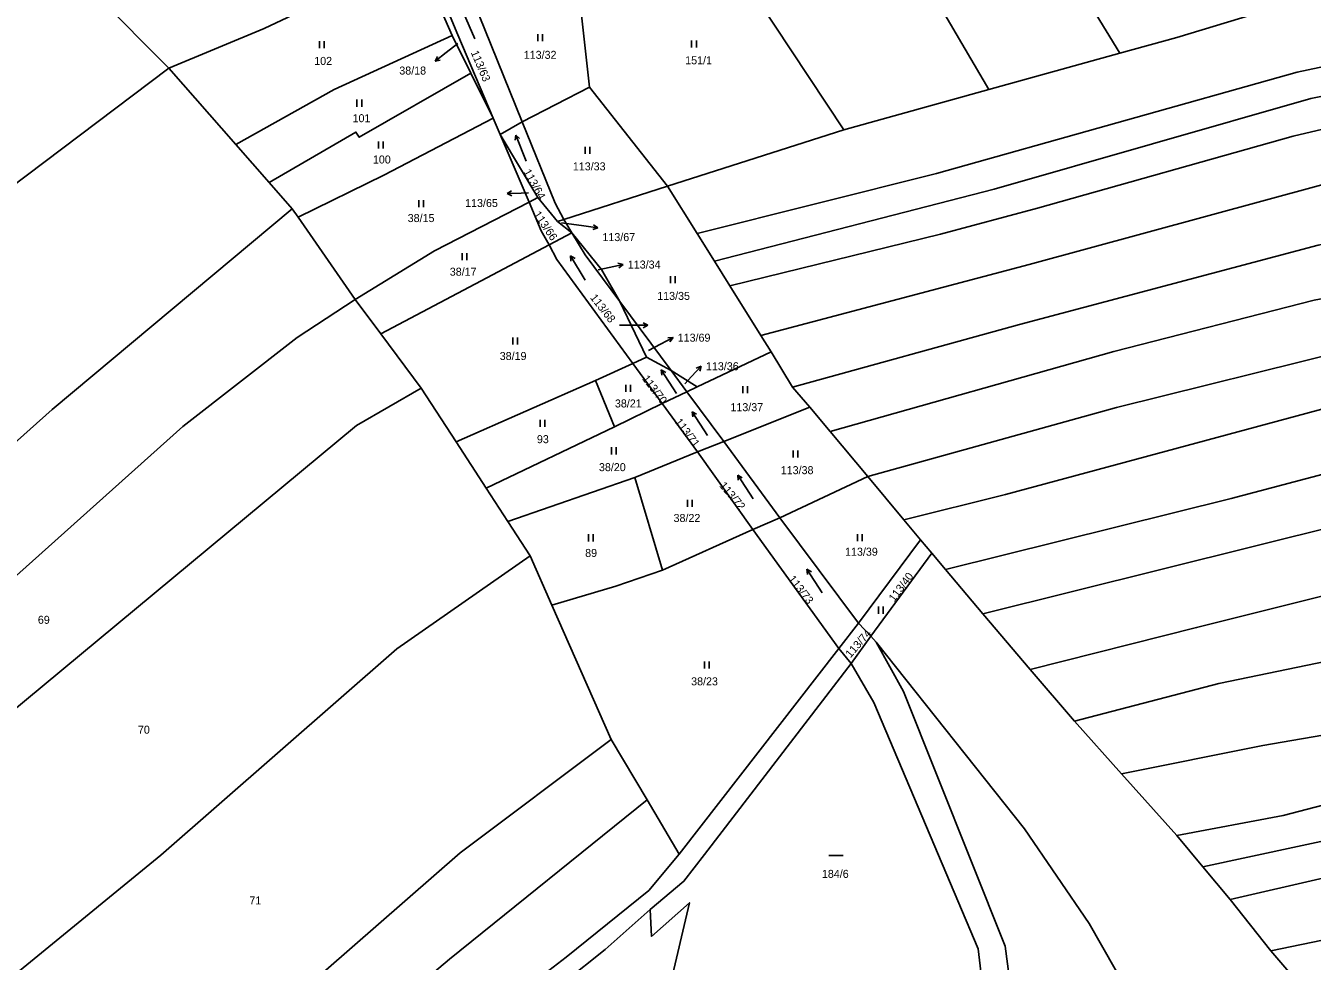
# Model space of a CAD drawing. Extents: x -7483133 to -743907, y -11317770 to -1129777.
# Drawn here: x -747509.1 to -747235.8, y -1131378.7 to -1131180 of the extents above; entities that cross this region are included whole.
import ezdxf

# ---------------------------------------------------------------- set-up
doc = ezdxf.new("R2010")
doc.units = 0
for name, color, linetype in [('Hranice parcel', 7, 'Continuous'), ('Parcelní čísla', 7, 'Continuous'), ('Pop  PČ popisy', 7, 'Continuous'), ('Značky kultur', 7, 'Continuous')]:
    doc.layers.add(name, color=color, linetype=linetype)

msp = doc.modelspace()

# ---------------------------------------------------------------- linework, layer by layer
at = {"layer": 'Hranice parcel'}
for p, q in [((-747414.16, -1131174.44), (-747403.63, -1131200.37)), ((-747389.33, -1131193.02), (-747391.42, -1131174.47)), ((-747420.83, -1131176.75), (-747418.53, -1131182.09)), ((-747418.53, -1131182.09), (-747414.55, -1131190.08)), ((-747304.55, -1131193.5), (-747276.68, -1131185.78)), ((-747464.5, -1131205.17), (-747478.68, -1131189)), ((-747414.55, -1131190.08), (-747409.79, -1131199.63)), ((-747403.63, -1131200.37), (-747389.33, -1131193.02)), ((-747372.79, -1131214.07), (-747389.33, -1131193.02)), ((-747335.3, -1131202.07), (-747304.55, -1131193.5)), ((-747408.32, -1131203.08), (-747409.79, -1131199.63)), ((-747408.32, -1131203.08), (-747403.63, -1131200.37)), ((-747402.18, -1131217.46), (-747408.32, -1131203.08)), ((-747408.32, -1131203.08), (-747400.3, -1131216.43)), ((-747372.79, -1131214.07), (-747335.3, -1131202.07)), ((-747457.41, -1131213.25), (-747464.5, -1131205.17)), ((-747452.5, -1131218.84), (-747457.41, -1131213.25)), ((-747394.81, -1131221.1), (-747372.79, -1131214.07)), ((-747366.49, -1131224.14), (-747372.79, -1131214.07)), ((-747402.18, -1131217.46), (-747400.3, -1131216.43)), ((-747400.3, -1131216.43), (-747396.13, -1131221.54)), ((-747451.24, -1131220.66), (-747452.5, -1131218.84)), ((-747451.24, -1131220.66), (-747439.12, -1131238.12)), ((-747396.13, -1131221.54), (-747394.81, -1131221.1)), ((-747393.08, -1131223.94), (-747396.13, -1131221.54)), ((-747394.81, -1131221.1), (-747393.08, -1131223.94)), ((-747397.95, -1131226.54), (-747393.08, -1131223.94)), ((-747362.83, -1131229.98), (-747366.49, -1131224.14)), ((-747359.55, -1131235.22), (-747362.83, -1131229.98)), ((-747352.93, -1131245.79), (-747359.55, -1131235.22)), ((-747439.12, -1131238.12), (-747433.68, -1131245.43)), ((-747377.23, -1131250.36), (-747382.92, -1131238.52)), ((-747382.92, -1131238.52), (-747372.02, -1131253.19)), ((-747433.68, -1131245.43), (-747425.11, -1131256.95)), ((-747350.79, -1131249.21), (-747352.93, -1131245.79)), ((-747380.11, -1131251.72), (-747377.23, -1131250.36)), ((-747377.23, -1131250.36), (-747372.02, -1131253.19)), ((-747366.48, -1131256.66), (-747350.79, -1131249.21)), ((-747346.25, -1131256.73), (-747350.79, -1131249.21)), ((-747388.07, -1131255.34), (-747380.11, -1131251.72)), ((-747373.91, -1131260.21), (-747380.11, -1131251.72)), ((-747372.02, -1131253.19), (-747366.48, -1131256.66)), ((-747372.02, -1131253.19), (-747368.67, -1131257.7)), ((-747417.7, -1131268.35), (-747388.07, -1131255.34)), ((-747388.07, -1131255.34), (-747384.01, -1131265.18)), ((-747425.11, -1131256.95), (-747417.7, -1131268.35)), ((-747373.91, -1131260.21), (-747368.67, -1131257.7)), ((-747368.67, -1131257.7), (-747366.48, -1131256.66)), ((-747368.67, -1131257.7), (-747360.8, -1131268.29)), ((-747342.53, -1131260.96), (-747346.25, -1131256.73)), ((-747373.91, -1131260.21), (-747384.01, -1131265.18)), ((-747366.42, -1131270.45), (-747373.91, -1131260.21)), ((-747360.8, -1131268.29), (-747342.53, -1131260.96)), ((-747338.19, -1131266.17), (-747342.53, -1131260.96)), ((-747384.01, -1131265.18), (-747411.33, -1131278.16)), ((-747330.24, -1131275.71), (-747338.19, -1131266.17)), ((-747411.33, -1131278.16), (-747417.7, -1131268.35)), ((-747366.42, -1131270.45), (-747360.8, -1131268.29)), ((-747360.8, -1131268.29), (-747348.89, -1131284.46)), ((-747379.74, -1131275.95), (-747366.42, -1131270.45)), ((-747354.67, -1131286.99), (-747366.42, -1131270.45)), ((-747348.89, -1131284.46), (-747330.24, -1131275.71)), ((-747322.57, -1131284.9), (-747330.24, -1131275.71)), ((-747411.33, -1131278.16), (-747406.7, -1131285.28)), ((-747406.7, -1131285.28), (-747379.74, -1131275.95)), ((-747379.74, -1131275.95), (-747373.86, -1131295.58)), ((-747401.97, -1131292.55), (-747406.7, -1131285.28)), ((-747354.67, -1131286.99), (-747348.89, -1131284.46)), ((-747348.89, -1131284.46), (-747332.21, -1131306.86)), ((-747319.02, -1131289.16), (-747322.57, -1131284.9)), ((-747373.86, -1131295.58), (-747354.67, -1131286.99)), ((-747336.38, -1131312.26), (-747354.67, -1131286.99)), ((-747332.21, -1131306.86), (-747319.02, -1131289.16)), ((-747316.65, -1131292.01), (-747319.02, -1131289.16)), ((-747316.65, -1131292.01), (-747329.56, -1131309.63)), ((-747313.75, -1131295.48), (-747316.65, -1131292.01)), ((-747397.34, -1131303.04), (-747401.97, -1131292.55)), ((-747305.83, -1131304.88), (-747313.75, -1131295.48)), ((-747397.34, -1131303.04), (-747384.78, -1131331.55)), ((-747295.77, -1131316.67), (-747305.83, -1131304.88)), ((-747336.38, -1131312.26), (-747332.21, -1131306.86)), ((-747332.21, -1131306.86), (-747329.56, -1131309.63)), ((-747329.56, -1131309.63), (-747333.76, -1131315.41)), ((-747328.48, -1131310.88), (-747329.56, -1131309.63)), ((-747370.27, -1131355.92), (-747336.38, -1131312.26)), ((-747333.76, -1131315.41), (-747336.38, -1131312.26)), ((-747286.32, -1131327.71), (-747295.77, -1131316.67)), ((-747276.35, -1131338.85), (-747286.32, -1131327.71)), ((-747384.78, -1131331.55), (-747377.13, -1131344.4)), ((-747264.6, -1131351.98), (-747276.35, -1131338.85)), ((-747377.13, -1131344.4), (-747370.27, -1131355.92)), ((-747259.05, -1131358.62), (-747264.6, -1131351.98)), ((-747253.26, -1131365.55), (-747259.05, -1131358.62)), ((-747244.62, -1131376.47), (-747253.26, -1131365.55)), ((-747233.02, -1131389.89), (-747244.62, -1131376.47))]:
    msp.add_line(p, q, dxfattribs=at)
for points in [[(-747455.08, -1130941.09), (-747407, -1130998.24), (-747346.3, -1131076.82), (-747308.86, -1131133.19), (-747276.68, -1131185.78)], [(-747466.65, -1130957.41), (-747426.05, -1131003.14), (-747390.52, -1131051.98), (-747379.77, -1131069.99), (-747357.62, -1131107.84), (-747342.16, -1131135.57), (-747326.23, -1131160.19), (-747318.42, -1131169.83), (-747304.55, -1131193.5)], [(-747376.22, -1131135.6), (-747368.67, -1131151.69), (-747335.3, -1131202.07)], [(-747366.49, -1131224.14), (-747315.64, -1131211.37), (-747239.01, -1131189.85), (-747208.02, -1131183.24), (-747142.94, -1131169.86), (-747059.23, -1131151.85), (-746994.26, -1131139.92)], [(-747362.83, -1131229.98), (-747303.37, -1131214.71), (-747236.14, -1131195.43), (-747183.65, -1131184.91), (-747140.79, -1131175.19), (-747094.5, -1131166.43), (-747035.79, -1131154.71), (-746990.07, -1131145.5)], [(-747359.55, -1131235.22), (-747314.76, -1131224.28), (-747294.21, -1131218.7), (-747239.88, -1131203.41), (-747217.65, -1131198.22), (-747179.1, -1131189.54), (-747110.35, -1131174.95), (-747094.58, -1131172.24), (-747057.06, -1131164.91), (-746987.65, -1131152.16)], [(-747478.68, -1131189), (-747493.84, -1131173.69), (-747508, -1131163.09)], [(-747352.93, -1131245.79), (-747295.96, -1131230.66), (-747233.75, -1131213.76), (-747157.12, -1131196.99), (-747060.9, -1131176.27), (-747030, -1131171.43), (-746983.59, -1131163.34)], [(-747425.84, -1131165.11), (-747458.47, -1131180.59), (-747478.68, -1131189)], [(-747409.79, -1131199.63), (-747417.35, -1131181.9), (-747419.66, -1131176.34)], [(-747346.25, -1131256.73), (-747297.98, -1131243.4), (-747234.57, -1131226.59), (-747209.63, -1131221.41), (-747174.99, -1131213.76), (-747135.39, -1131204.28), (-747094.05, -1131195.6), (-747052.94, -1131188.25), (-746980.29, -1131175.39)], [(-747276.68, -1131185.78), (-747264.57, -1131182.48), (-747243.06, -1131175.98)], [(-747418.53, -1131182.09), (-747443.59, -1131193.55), (-747464.5, -1131205.17)], [(-747338.19, -1131266.17), (-747277.98, -1131249.2), (-747235.43, -1131238.28), (-747213.21, -1131234.14), (-747187.16, -1131228.96), (-747140.48, -1131218.28), (-747086.15, -1131207.37), (-747047.59, -1131199.64), (-746976.21, -1131185.45)], [(-747478.68, -1131189), (-747516.61, -1131217.55), (-747562.75, -1131257.36), (-747584.62, -1131275.69), (-747613.72, -1131296.16)], [(-747414.55, -1131190.08), (-747438.27, -1131203.66), (-747438.96, -1131202.58), (-747457.41, -1131213.25)], [(-747330.24, -1131275.71), (-747277.42, -1131261.08), (-747228.35, -1131248.89), (-747189.96, -1131241.4), (-747149.33, -1131232.63), (-747125.6, -1131227.7), (-747062.34, -1131215.02), (-746993.98, -1131202.44), (-746969.25, -1131197.46)], [(-747409.79, -1131199.63), (-747433.07, -1131211.69), (-747451.24, -1131220.66)], [(-747403.63, -1131200.37), (-747396.62, -1131217.65), (-747394.81, -1131221.1)], [(-747322.57, -1131284.9), (-747301.01, -1131279.52), (-747228.28, -1131259.93), (-747190.83, -1131253.47), (-747160.64, -1131247.09), (-747111.02, -1131236.65), (-747064.81, -1131227), (-747042.19, -1131222.79), (-746964.73, -1131206.9)], [(-747439.12, -1131238.12), (-747422.3, -1131227.8), (-747402.18, -1131217.46)], [(-747397.95, -1131226.54), (-747399.59, -1131223.53), (-747402.18, -1131217.46)], [(-747587.97, -1131330.74), (-747567.99, -1131317.8), (-747522.26, -1131278.21), (-747503.48, -1131261.46), (-747452.5, -1131218.84)], [(-747313.75, -1131295.48), (-747253.05, -1131280.4), (-747231.07, -1131274.58), (-747201.09, -1131268.16), (-747174.02, -1131263.18), (-747155.54, -1131259.35), (-747082.77, -1131244.23), (-747040.5, -1131235.77), (-746958.82, -1131219.23)], [(-747433.68, -1131245.43), (-747412.33, -1131234.19), (-747397.95, -1131226.54)], [(-747380.11, -1131251.72), (-747396.26, -1131229.64), (-747397.95, -1131226.54)], [(-747393.08, -1131223.94), (-747390.29, -1131228.61), (-747382.92, -1131238.52)], [(-747382.92, -1131238.52), (-747386.77, -1131231.73), (-747393.08, -1131223.94)], [(-747305.83, -1131304.88), (-747229.31, -1131285.82), (-747172.59, -1131275.8), (-747161.6, -1131273.01), (-747136.9, -1131266.58), (-747124.63, -1131263.55), (-747104.54, -1131259.94), (-747060.99, -1131251.11), (-747007.85, -1131241), (-746953.9, -1131229.5)], [(-747573.75, -1131348.78), (-747519.29, -1131304), (-747475.75, -1131265.13), (-747451.48, -1131246.17), (-747439.12, -1131238.12)], [(-747295.77, -1131316.67), (-747260.4, -1131307.82), (-747220.48, -1131297.78), (-747153.89, -1131284.38), (-747109.03, -1131274.27), (-747084.89, -1131269.09), (-747048.4, -1131261.6), (-746996.46, -1131251.25), (-746948.48, -1131240.82)], [(-747286.32, -1131327.71), (-747255.69, -1131319.66), (-747224.48, -1131313.25), (-747107.43, -1131287.3), (-747063.05, -1131278.04), (-746994.13, -1131264.35), (-746941.49, -1131255.09)], [(-747560.74, -1131366.12), (-747532.83, -1131342.86), (-747438.82, -1131264.87), (-747425.11, -1131256.95)], [(-747276.35, -1131338.85), (-747246.32, -1131332.88), (-747229.43, -1131329.93), (-747186.72, -1131322.04), (-747161.79, -1131317.33), (-747140.27, -1131312.31), (-747078.52, -1131295.97), (-747046.25, -1131288.56), (-746999.24, -1131278.2), (-746933.58, -1131266.63)], [(-747264.6, -1131351.98), (-747242.03, -1131347.7), (-747213.19, -1131340.2), (-747179.96, -1131333.82), (-747146.25, -1131326.27), (-747116.44, -1131318.14), (-747074.2, -1131308.65), (-747023.69, -1131297.62), (-746995.16, -1131291.67), (-746955.56, -1131282.99), (-746925.84, -1131277.49)], [(-747259.05, -1131358.62), (-747228.4, -1131352.04), (-747205.77, -1131347.04), (-747151.5, -1131335.64), (-747117.4, -1131325.2), (-747070.07, -1131315.07), (-747039.71, -1131308.46), (-746993.82, -1131298.66), (-746944.81, -1131287.98), (-746923.42, -1131282.84)], [(-747253.26, -1131365.55), (-747212.4, -1131356.17), (-747193.75, -1131352.82), (-747152.23, -1131344.41), (-747118.92, -1131334.29), (-747064.98, -1131321.22), (-747047.21, -1131317.79), (-747015.97, -1131311.89), (-746983.3, -1131303.76), (-746958.12, -1131297.54), (-746919.95, -1131289.65)], [(-747534.26, -1131400.17), (-747480.38, -1131356.14), (-747430.3, -1131312.29), (-747401.97, -1131292.55)], [(-747373.86, -1131295.58), (-747383.75, -1131299), (-747397.34, -1131303.04)], [(-747244.62, -1131376.47), (-747194.94, -1131366.2), (-747152.47, -1131357.99), (-747132.71, -1131352.21), (-747080.19, -1131338.5), (-747060.42, -1131333.39), (-747013.88, -1131325.1), (-746957.78, -1131310.91), (-746913.29, -1131301.58)], [(-747281.5, -1131480.62), (-747293.52, -1131448.9), (-747294.79, -1131442.89), (-747294.49, -1131425.32), (-747301.04, -1131375.44), (-747322.63, -1131321.35), (-747328.48, -1131310.88)], [(-747281.5, -1131480.62), (-747268.38, -1131439.1), (-747266.03, -1131410.81), (-747274.76, -1131385.48), (-747283.22, -1131370.63), (-747296.93, -1131350.55), (-747328.48, -1131310.88)], [(-747333.76, -1131315.41), (-747364.89, -1131355.97), (-747369.3, -1131361.68), (-747376.46, -1131367.68)], [(-747333.76, -1131315.41), (-747328.97, -1131323.74), (-747306.78, -1131376.04), (-747305.04, -1131391.08)], [(-747506.23, -1131431.25), (-747474.44, -1131405.95), (-747416.83, -1131355.62), (-747384.78, -1131331.55)], [(-747495.56, -1131443.68), (-747453.65, -1131407.36), (-747419.12, -1131378.23), (-747377.13, -1131344.4)], [(-747370.27, -1131355.92), (-747376.75, -1131363.63), (-747394.3, -1131377.78), (-747413.65, -1131392.68), (-747433.29, -1131410.44), (-747454.33, -1131429.09), (-747485.81, -1131454.98)], [(-747482.98, -1131458.6), (-747465.09, -1131443.35), (-747442.92, -1131423.66), (-747415.85, -1131400.46), (-747394.73, -1131383.14), (-747385.99, -1131376.16), (-747376.46, -1131367.68)], [(-747376.46, -1131367.68), (-747376.16, -1131373.4), (-747368.11, -1131366.26), (-747372.26, -1131384.03)]]:
    msp.add_lwpolyline(points, dxfattribs=at)
at = {"layer": 'Pop  PČ popisy'}
for p, q in [((-747417.31, -1131183.76), (-747419.78, -1131185.67)), ((-747419.78, -1131185.67), (-747422.15, -1131187.52)), ((-747422.15, -1131187.52), (-747421.66, -1131186.51)), ((-747422.15, -1131187.52), (-747421.05, -1131187.3)), ((-747406.87, -1131215.61), (-747405.89, -1131215.08)), ((-747403.87, -1131215.51), (-747406.87, -1131215.61)), ((-747406.87, -1131215.61), (-747405.85, -1131216.08)), ((-747402.28, -1131215.44), (-747403.87, -1131215.51)), ((-747395.32, -1131221.83), (-747390.57, -1131222.47)), ((-747390.57, -1131222.47), (-747387.6, -1131222.89)), ((-747387.6, -1131222.89), (-747388.66, -1131223.24)), ((-747387.6, -1131222.89), (-747388.52, -1131222.25)), ((-747387.54, -1131231.81), (-747385.15, -1131231.31)), ((-747385.15, -1131231.31), (-747382.21, -1131230.69)), ((-747382.21, -1131230.69), (-747383.3, -1131230.4)), ((-747382.21, -1131230.69), (-747383.09, -1131231.38)), ((-747376.82, -1131248.99), (-747374.26, -1131247.63)), ((-747374.26, -1131247.63), (-747371.61, -1131246.22)), ((-747371.61, -1131246.22), (-747372.73, -1131246.25)), ((-747371.61, -1131246.22), (-747372.26, -1131247.13)), ((-747367.66, -1131254.49), (-747365.61, -1131252.29)), ((-747365.61, -1131252.29), (-747366.66, -1131252.69)), ((-747365.61, -1131252.29), (-747365.93, -1131253.37)), ((-747369.1, -1131256.04), (-747367.66, -1131254.49))]:
    msp.add_line(p, q, dxfattribs=at)
at = {"layer": 'Značky kultur'}
for p, q in [((-747413.68, -1131182.75), (-747416.12, -1131177.27)), ((-747400.35, -1131183.28), (-747400.35, -1131181.78)), ((-747399.35, -1131183.28), (-747399.35, -1131181.78)), ((-747446.72, -1131184.75), (-747446.72, -1131183.25)), ((-747445.72, -1131184.75), (-747445.72, -1131183.25)), ((-747367.65, -1131184.63), (-747367.65, -1131183.13)), ((-747366.65, -1131184.63), (-747366.65, -1131183.13)), ((-747438.74, -1131197.17), (-747438.74, -1131195.67)), ((-747437.74, -1131197.17), (-747437.74, -1131195.67)), ((-747434.17, -1131206.06), (-747434.17, -1131204.56)), ((-747433.17, -1131206.06), (-747433.17, -1131204.56)), ((-747405.02, -1131203.2), (-747405.12, -1131204.29)), ((-747402.78, -1131208.76), (-747405.02, -1131203.2)), ((-747405.02, -1131203.2), (-747404.19, -1131203.92)), ((-747390.28, -1131207.21), (-747390.28, -1131205.71)), ((-747389.28, -1131207.21), (-747389.28, -1131205.71)), ((-747425.63, -1131218.5), (-747425.63, -1131217)), ((-747424.63, -1131218.5), (-747424.63, -1131217)), ((-747416.42, -1131229.77), (-747416.42, -1131228.27)), ((-747415.42, -1131229.77), (-747415.42, -1131228.27)), ((-747390.27, -1131234), (-747393.36, -1131228.86)), ((-747393.36, -1131228.86), (-747393.28, -1131229.96)), ((-747393.36, -1131228.86), (-747392.42, -1131229.44)), ((-747372.15, -1131234.66), (-747372.15, -1131233.16)), ((-747371.15, -1131234.66), (-747371.15, -1131233.16)), ((-747382.94, -1131243.61), (-747376.94, -1131243.61)), ((-747376.94, -1131243.61), (-747377.92, -1131243.11)), ((-747376.94, -1131243.61), (-747377.92, -1131244.11)), ((-747405.62, -1131247.67), (-747405.62, -1131246.17)), ((-747404.62, -1131247.67), (-747404.62, -1131246.17)), ((-747370.84, -1131258.1), (-747374.11, -1131253.06)), ((-747374.11, -1131253.06), (-747373.99, -1131254.16)), ((-747374.11, -1131253.06), (-747373.15, -1131253.61)), ((-747381.66, -1131257.75), (-747381.66, -1131256.25)), ((-747380.66, -1131257.75), (-747380.66, -1131256.25)), ((-747356.81, -1131258.04), (-747356.81, -1131256.54)), ((-747355.81, -1131258.04), (-747355.81, -1131256.54)), ((-747364.28, -1131266.98), (-747367.55, -1131261.95)), ((-747367.55, -1131261.95), (-747367.43, -1131263.04)), ((-747367.55, -1131261.95), (-747366.59, -1131262.49)), ((-747399.86, -1131265.2), (-747399.86, -1131263.7)), ((-747398.86, -1131265.2), (-747398.86, -1131263.7)), ((-747384.65, -1131271.02), (-747384.65, -1131269.52)), ((-747383.65, -1131271.02), (-747383.65, -1131269.52)), ((-747346.06, -1131271.67), (-747346.06, -1131270.17)), ((-747345.06, -1131271.67), (-747345.06, -1131270.17)), ((-747354.6, -1131280.46), (-747357.87, -1131275.43)), ((-747357.87, -1131275.43), (-747357.75, -1131276.52)), ((-747357.87, -1131275.43), (-747356.91, -1131275.97)), ((-747368.52, -1131282.18), (-747368.52, -1131280.68)), ((-747367.52, -1131282.18), (-747367.52, -1131280.68)), ((-747389.55, -1131289.49), (-747389.55, -1131287.99)), ((-747388.55, -1131289.49), (-747388.55, -1131287.99)), ((-747332.42, -1131289.43), (-747332.42, -1131287.93)), ((-747331.42, -1131289.43), (-747331.42, -1131287.93)), ((-747339.9, -1131300.44), (-747343.17, -1131295.41)), ((-747343.17, -1131295.41), (-747343.05, -1131296.5)), ((-747343.17, -1131295.41), (-747342.21, -1131295.95)), ((-747327.98, -1131304.85), (-747327.98, -1131303.35)), ((-747326.98, -1131304.85), (-747326.98, -1131303.35)), ((-747364.9, -1131316.52), (-747364.9, -1131315.02)), ((-747363.9, -1131316.52), (-747363.9, -1131315.02)), ((-747338.48, -1131356.23), (-747335.48, -1131356.23))]:
    msp.add_line(p, q, dxfattribs=at)

# ---------------------------------------------------------------- texts
at = {"layer": 'Parcelní čísla'}
for s, rotation, p in [('113/63', 293, (-747414.6, -1131185.65)), ('113/64', 299, (-747403.45, -1131210.99)), ('113/66', 304, (-747401.33, -1131220.04)), ('113/68', 308, (-747389.31, -1131237.77)), ('113/70', 307, (-747378.26, -1131254.96)), ('113/71', 307, (-747371.32, -1131264.14)), ('113/72', 310, (-747361.86, -1131277.71)), ('113/73', 308, (-747347.22, -1131297.52)), ('113/40', 53, (-747324.61, -1131302.46)), ('113/74', 49, (-747333.89, -1131314.34))]:
    msp.add_text(s, height=1.7, rotation=rotation, dxfattribs=at).set_placement(p)
for s, p in [('113/32', (-747403.31, -1131187.01)), ('102', (-747447.82, -1131188.3)), ('151/1', (-747369.02, -1131188.17)), ('38/18', (-747429.75, -1131190.35)), ('101', (-747439.68, -1131200.47)), ('100', (-747435.36, -1131209.24)), ('113/33', (-747392.89, -1131210.7)), ('113/65', (-747415.77, -1131218.48)), ('38/15', (-747427.97, -1131221.68)), ('113/67', (-747386.6, -1131225.72)), ('38/17', (-747419.03, -1131233.07)), ('113/34', (-747381.21, -1131231.55)), ('113/35', (-747374.96, -1131238.21)), ('113/69', (-747370.61, -1131247.08)), ('38/19', (-747408.42, -1131250.98)), ('113/36', (-747364.61, -1131253.15)), ('38/21', (-747383.95, -1131261.05)), ('113/37', (-747359.41, -1131261.84)), ('93', (-747400.52, -1131268.64)), ('38/20', (-747387.34, -1131274.58)), ('113/38', (-747348.72, -1131275.22)), ('38/22', (-747371.49, -1131285.37)), ('89', (-747390.27, -1131292.8)), ('113/39', (-747335.06, -1131292.54)), ('69', (-747506.53, -1131307)), ('38/23', (-747367.76, -1131320.07)), ('70', (-747485.27, -1131330.34)), ('184/6', (-747339.98, -1131360.96)), ('71', (-747461.6, -1131366.6))]:
    msp.add_text(s, height=1.7, dxfattribs=at).set_placement(p)

doc.saveas('drawing.dxf')
